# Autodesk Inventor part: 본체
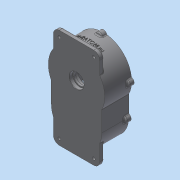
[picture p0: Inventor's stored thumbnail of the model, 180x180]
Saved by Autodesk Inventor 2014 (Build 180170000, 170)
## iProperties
Created: 2025-09
Part Number: 본체
Material: 일반
Document SubType Name: Modeling
Designer: dg
Density: 1 g/cm^3
Appearance: 기본값
Mass: 584.528 g
Surface Area: 1291.41 cm^2
Volume: 584.528 cm^3
Author: dg
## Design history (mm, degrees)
sketch "스케치1"
  geometry: L1 (55, 118.5)-(-55, 118.5); L2 (-55, 118.5)-(-55, -118.5); L3 (-55, -118.5)-(55, -118.5); L4 (55, -118.5)-(55, 118.5); L5 (55, 118.5)-(-55, -118.5); L6 (-55, 118.5)-(55, -118.5); L7 (50, -42.5)-(50, 8.132); L8 (-50, -42.5)-(-50, 8.132); L9 (-60, -42.5)-(-60, 5.684); L10 (60, 5.684)-(60, -42.5); A1 r 57 centre (0, 35.5) between (50, 8.132) and (-50, 8.132); A2 r 50 centre (0, -42.5) between (-50, -42.5) and (50, -42.5); A3 r 60 centre (0, -42.5) between (-60, -42.5) and (60, -42.5); A4 r 67 centre (0, 35.5) between (60, 5.684) and (-60, 5.684); 2 further points
  constraints: 20 end point, 8 point on circle, 5 parallel, 4 centre point, 3 midpoint, 2 tangent, 2 vertical alignment, 1 horizontal, 1 perpendicular, 3 other
  dimensions: "d0" = 110 distance of L2.end L3.end; "d1" = 237 distance of L3.end L1.start; "d3" = 114 diameter of A1; "d4" = 78 distance of A2.centre A1.centre; "d5" = 76 distance from line of L3 A2.centre; "d7" = 50 radius of A2; "d8" = 10 radial gap between concentric circles of A2 A3
extrude "돌출1" new body sketch "스케치1" distance "d9" = 10; taper "d10" = 0 deg
extrude "돌출2" join sketch "스케치1" distance "d11" = 64; taper "d12" = 0 deg
sketch "스케치2"
  geometry: L1 (-60, 42.5)-(-60, -5.684) reference; L2 (60, -5.684)-(60, 42.5) reference; L3 (50, 42.5)-(50, -8.132); L4 (-50, -8.132)-(-50, 42.5); A1 r 60 centre (0, 42.5) between (60, 42.5) and (-60, 42.5) reference; A2 r 67 centre (0, -35.5) between (-60, -5.684) and (60, -5.684) reference; A3 r 50 centre (0, 42.5) between (50, 42.5) and (-50, 42.5); A4 r 57 centre (0, -35.5) between (-50, -8.132) and (50, -8.132); 1 further point
  constraints: 4 end point, 4 point on circle, 2 centre point, 3 other
  dimensions: "d13" = 10 radial gap between concentric circles of A1 A3
extrude "돌출3" cut sketch "스케치2" distance "d14" = 54; taper "d15" = 0 deg
sketch "스케치3"
  geometry: C1 r 23.5 at (0, 42.5); C2 r 23.5 at (0, -35.5); A1 r 50 centre (0, 42.5) between (50, 42.5) and (-50, 42.5) reference; A2 r 57 centre (0, -35.5) between (-50, -8.132) and (50, -8.132) reference; 1 further point
  constraints: 2 centre point, 2 coincident
  dimensions: "d16" = 47 diameter of C1; "d17" = 47 diameter of C2
extrude "돌출4" join sketch "스케치3" distance "d18" = 26; taper "d19" = 0 deg
extrude "돌출5" join sketch "스케치3" distance "d20" = 12; taper "d21" = 0 deg
sketch "스케치5"
  geometry: L1 (36, -66)-(36, -19) reference; L2 (0, -42.5)-(0, -66.479) reference; L3 (0, -42.5)-(0, 5.684) reference; L4 (36, -42.5)-(0, -42.5); L5 (36, -61)-(27, -61); L6 (27, -61)-(27, -58.5); L7 (27, -58.5)-(11, -58.5); L8 (11, -58.5)-(11, -56.5); L9 (11, -56.5)-(8, -56.5); L10 (8, -56.5)-(8, -42.5); L11 (22, 12)-(22, 59) reference; L12 (0, 73.762)-(0, 5.684) reference; L13 (22, 35.5)-(0, 35.5); L14 (0, 18)-(8.3, 18); L15 (8.3, 18)-(8.3, 20.5); L16 (8.3, 20.5)-(13, 20.5); L17 (13, 20.5)-(13, 17); L18 (13, 17)-(22, 17); 1 further point
  constraints: 26 end point, 7 parallel, 6 perpendicular, 5 point on line, 2 midpoint
  dimensions: "d22" = 37 diameter of L5 L4; "d23" = 32 diameter of L7 L4; "d24" = 28 diameter of L9 L4; "d25" = 9 distance of L5.start L5.end; "d26" = 16 distance of L6.end L7.end; "d27" = 3 distance of L8.end L9.end; "d28" = 37 diameter of L18 L13; "d29" = 30 diameter of L16 L13; "d30" = 35 diameter of L14 L13; "d31" = 9 distance of L17.end L18.end; "d32" = 8.3 distance of L14.start L14.end
revolve "회전1" stored, may be unused: angle "d33" = 90 deg
revolve "회전2" stored, may be unused: angle "d34" = 90 deg
fillet "모깎기1" dims "d35" = 14
sketch "스케치6"
  geometry: A1 r 14 centre (41, -104.5) between (41, -118.5) and (55, -104.5) reference; A2 r 14 centre (-41, -104.5) between (-55, -104.5) and (-41, -118.5) reference; A3 r 14 centre (-41, 104.5) between (-41, 118.5) and (-55, 104.5) reference; A4 r 14 centre (41, 104.5) between (55, 104.5) and (41, 118.5) reference; 1 further point
hole "구멍1" sketch "스케치6" at (-41, -104.5), (41, -104.5), (-41, 104.5), (41, 104.5) diameter "d36" = 6.6; stored, may be unused: countersink angle "d40" = 90 deg, drill point angle "d42" = 118 deg; dims "d37" = 6, "d38" = 18, "d39" = 2, "d41" = 8
chamfer "모따기1" distance "d53" = 1; stored, may be unused: second distance "d54" = 2, angle "d55" = 45 deg
fillet "모깎기2" dims "d56" = 0.3
chamfer "모따기2" distance "d57" = 0.8; stored, may be unused: second distance "d58" = 2, angle "d59" = 30 deg
fillet "모깎기5" dims "d62" = 3
fillet "모깎기6" dims "d63" = 3
fillet "모깎기7" dims "d64" = 3
fillet "모깎기8" dims "d65" = 3
fillet "모깎기9" dims "d66" = 13
fillet "모깎기10" dims "d67" = 3
fillet "모깎기11" dims "d68" = 3
fillet "모깎기12" dims "d72" = 3
fillet "모깎기13" dims "d73" = 0.3
sketch "스케치10"
  geometry: C1 r 8 at (-58, 42.5); C2 r 8 at (58, 42.5); C3 r 8 at (-65, -35.5); C4 r 8 at (65, -35.5); C5 r 8 at (0, 100.5); C6 r 8 at (0, -100.5); A1 r 50 centre (0, 42.5) between (50, 42.5) and (-50, 42.5) reference; A2 r 57 centre (0, -35.5) between (-51.3, -10.654) and (51.3, -10.654) reference; A3 r 60 centre (0, 42.5) between (60, 42.5) and (-60, 42.5) reference; 4 further points
  constraints: 6 centre point, 4 horizontal alignment, 2 vertical alignment, 1 other
  dimensions: "d74" = 16 diameter of C1; "d75" = 16 diameter of C2; "d76" = 116 distance of C1.centre C2.centre; "d77" = 58 distance of A1.centre C1.centre (= 0.5 x d76); "d78" = 16 diameter of C3; "d79" = 16 diameter of C4; "d80" = 130 distance of C3.centre C4.centre; "d81" = 65 distance of A2.centre C3.centre (= 0.5 x d80); "d82" = 16 diameter of C5; "d83" = 16 diameter of C6; "d84" = 58 distance of A1.centre C5.centre; "d85" = 65 distance of C6.centre A2.centre
extrude "돌출7" join sketch "스케치10" distance "d86" = 12; taper "d87" = 0 deg
sketch "스케치11"
  geometry: A1 r 8 centre (65, -35.5) between (66.538, -43.351) and (66.538, -27.649) reference; A2 r 8 centre (58, 42.5) between (60, 34.754) and (59.483, 50.361) reference; A3 r 8 centre (0, 100.5) between (7.861, 101.983) and (-7.861, 101.983) reference; A4 r 8 centre (-58, 42.5) between (-59.483, 50.361) and (-60, 34.754) reference; A5 r 8 centre (-65, -35.5) between (-66.538, -27.649) and (-66.538, -43.351) reference; A6 r 8 centre (0, -100.5) between (-7.851, -102.038) and (7.851, -102.038) reference; 1 further point
hole "구멍3" sketch "스케치11" at (58, 42.5), (65, -35.5), (0, -100.5), (-65, -35.5), (-58, 42.5), (0, 100.5) diameter "d88" = 3.242; stored, may be unused: countersink angle "d92" = 90 deg, drill point angle "d94" = 118 deg; dims "d89" = 8, "d90" = 18, "d91" = 2, "d93" = 10
fillet "모깎기14" dims "d95" = 3
fillet "모깎기15" dims "d96" = 3
node "작업 평면2"
sketch "스케치12"
  geometry: L1 (-41, 0)-(41, 0) reference; L2 (55.514, 0)-(67, 0) reference; 4 further points
  constraints: 1 midpoint, 1 vertical alignment, 1 other
  dimensions: "d97" = 30 distance from line of point (0, 30) L2
feature "엠보싱2" sketch "스케치12" dims "d0" = 110, "d1" = 237, "d3" = 114, "d4" = 78, "d5" = 76, "d7" = 50, "d8" = 10, "d98" = 0.5, "d99" = 0
node "솔리드1"
